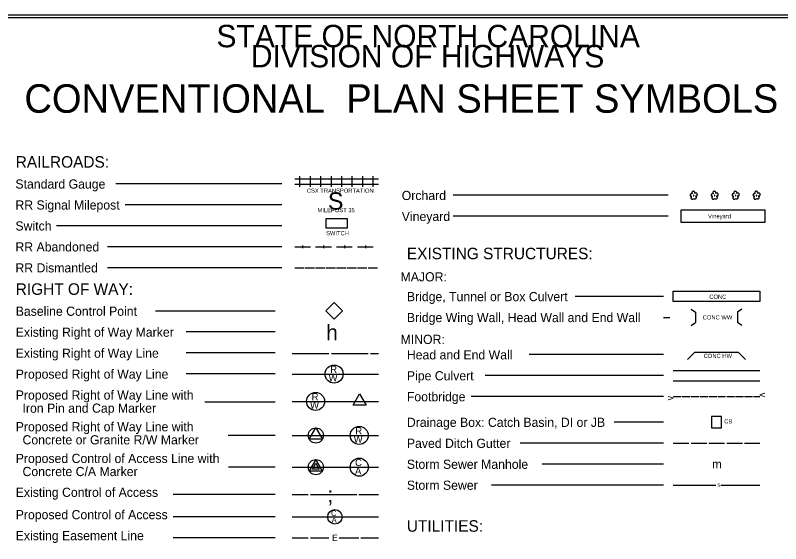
# Model space of a CAD drawing. Extents: x 1664524 to 1666208, y 587901 to 592296.
# Drawn here: x 1665085 to 1665816, y 589575 to 590079 of the extents above; entities that cross this region are included whole.
import ezdxf

# ---------------------------------------------------------------- set-up
doc = ezdxf.new("R2010")
doc.units = 0
for name, color, linetype in [('Default', 7, 'Continuous'), ('Prop Horizontal Alignment Tick Large', 7, 'Continuous'), ('Sheet Symbology CELL', 7, 'Continuous')]:
    doc.layers.add(name, color=color, linetype=linetype)

msp = doc.modelspace()

# ---------------------------------------------------------------- linework, layer by layer
at = {"layer": 'Default'}
msp.add_lwpolyline([(1665381.58, 589796.91), (1665389.4, 589804.73), (1665397.23, 589796.91), (1665389.4, 589789.08)], close=True, dxfattribs=at)
at = {"layer": 'Prop Horizontal Alignment Tick Large'}
msp.add_lwpolyline([(1664536.76, 589023.8), (1666203.26, 589023.8), (1666203.26, 590078.9), (1664536.76, 590078.9)], close=True, dxfattribs=at)
at = {"layer": 'Sheet Symbology CELL'}
for p, q in [((1665351.76, 589922.82), (1665361.76, 589922.82)), ((1665356.76, 589915.32), (1665356.76, 589925.32)), ((1665361.76, 589922.82), (1665371.76, 589922.82)), ((1665366.76, 589915.32), (1665366.76, 589925.32)), ((1665371.76, 589922.82), (1665381.76, 589922.82)), ((1665376.76, 589915.32), (1665376.76, 589925.32)), ((1665381.76, 589922.82), (1665391.76, 589922.82)), ((1665386.76, 589915.32), (1665386.76, 589925.32)), ((1665391.76, 589922.82), (1665401.76, 589922.82)), ((1665396.76, 589915.32), (1665396.76, 589925.32)), ((1665401.76, 589922.82), (1665411.76, 589922.82)), ((1665406.76, 589915.32), (1665406.76, 589925.32)), ((1665411.76, 589922.82), (1665421.76, 589922.82)), ((1665416.76, 589915.32), (1665416.76, 589925.32)), ((1665421.76, 589922.82), (1665431.76, 589922.82)), ((1665426.76, 589915.32), (1665426.76, 589925.32)), ((1665339.37, 589918.06), (1665180.95, 589918.06)), ((1665351.76, 589917.82), (1665361.76, 589917.82)), ((1665361.76, 589917.82), (1665371.76, 589917.82)), ((1665371.76, 589917.82), (1665381.76, 589917.82)), ((1665381.76, 589917.82), (1665391.76, 589917.82)), ((1665391.76, 589917.82), (1665401.76, 589917.82)), ((1665401.76, 589917.82), (1665411.76, 589917.82)), ((1665411.76, 589917.82), (1665421.76, 589917.82)), ((1665421.76, 589917.82), (1665431.76, 589917.82)), ((1665708.09, 589907.13), (1665503.15, 589907.13)), ((1665339.37, 589898.06), (1665189.82, 589898.06)), ((1665708.09, 589887.13), (1665503.15, 589887.13)), ((1665339.37, 589878.06), (1665124.45, 589878.06)), ((1665339.37, 589858.06), (1665173.2, 589858.06)), ((1665351.76, 589858.06), (1665366.76, 589858.06)), ((1665359.26, 589859.31), (1665359.26, 589856.81)), ((1665371.76, 589858.06), (1665386.76, 589858.06)), ((1665379.26, 589859.31), (1665379.26, 589856.81)), ((1665391.76, 589858.06), (1665406.76, 589858.06)), ((1665399.26, 589859.31), (1665399.26, 589856.81)), ((1665411.76, 589858.06), (1665426.76, 589858.06)), ((1665419.26, 589859.31), (1665419.26, 589856.81)), ((1665339.37, 589838.06), (1665173.2, 589838.06)), ((1665339.37, 589838.06), (1665173.2, 589838.06)), ((1665351.76, 589838.06), (1665360.76, 589838.06)), ((1665361.76, 589838.06), (1665370.76, 589838.06)), ((1665371.76, 589838.06), (1665380.76, 589838.06)), ((1665381.76, 589838.06), (1665390.76, 589838.06)), ((1665391.76, 589838.06), (1665400.76, 589838.06)), ((1665401.76, 589838.06), (1665410.76, 589838.06)), ((1665411.76, 589838.06), (1665420.76, 589838.06)), ((1665421.76, 589838.06), (1665430.76, 589838.06)), ((1665703.77, 589810.67), (1665619.35, 589810.67)), ((1665333.23, 589796.71), (1665219.02, 589796.71)), ((1665730.22, 589798.53), (1665734.32, 589795.67)), ((1665734.32, 589795.67), (1665734.32, 589785.67)), ((1665778.42, 589798.53), (1665774.32, 589795.67)), ((1665774.32, 589795.67), (1665774.32, 589785.67)), ((1665703.77, 589790.67), (1665709.76, 589790.67)), ((1665730.22, 589782.81), (1665734.32, 589785.67)), ((1665778.42, 589782.81), (1665774.32, 589785.67)), ((1665333.23, 589776.71), (1665248.29, 589776.71)), ((1665333.23, 589756.71), (1665248.29, 589756.71)), ((1665349.26, 589756.14), (1665384.26, 589756.14)), ((1665386.76, 589756.14), (1665421.76, 589756.14)), ((1665424.26, 589756.14), (1665431.76, 589756.14)), ((1665703.77, 589755.1), (1665575.47, 589755.1)), ((1665726.62, 589750.52), (1665733.7, 589757.6)), ((1665733.7, 589757.6), (1665774.95, 589757.6)), ((1665774.95, 589757.6), (1665782.02, 589750.52)), ((1665333.23, 589736.71), (1665248.29, 589736.71)), ((1665349.26, 589736.59), (1665431.76, 589736.59)), ((1665713.07, 589740.1), (1665795.57, 589740.1)), ((1665703.77, 589735.1), (1665533.59, 589735.1)), ((1665713.07, 589730.1), (1665795.57, 589730.1)), ((1665703.77, 589715.1), (1665520.3, 589715.1)), ((1665713.07, 589715.1), (1665720.57, 589715.1)), ((1665721.57, 589715.1), (1665729.07, 589715.1)), ((1665730.07, 589715.1), (1665737.57, 589715.1)), ((1665738.57, 589715.1), (1665746.07, 589715.1)), ((1665747.07, 589715.1), (1665754.57, 589715.1)), ((1665755.57, 589715.1), (1665763.07, 589715.1)), ((1665764.07, 589715.1), (1665771.57, 589715.1)), ((1665772.57, 589715.1), (1665780.07, 589715.1)), ((1665781.07, 589715.1), (1665788.57, 589715.1)), ((1665789.57, 589715.1), (1665795.57, 589715.1)), ((1665333.23, 589709.86), (1665266.12, 589709.86)), ((1665349.26, 589710.46), (1665431.76, 589710.46)), ((1665413.71, 589710.46), (1665413.71, 589710.46)), ((1665703.77, 589690.67), (1665656.57, 589690.67)), ((1665333.23, 589677.82), (1665288.24, 589677.82)), ((1665349.26, 589677.96), (1665431.76, 589677.96)), ((1665371.96, 589677.96), (1665371.96, 589677.96)), ((1665703.77, 589670.67), (1665566.82, 589670.67)), ((1665713.07, 589670.67), (1665728.07, 589670.67)), ((1665730.07, 589670.67), (1665745.07, 589670.67)), ((1665747.07, 589670.67), (1665762.07, 589670.67)), ((1665764.07, 589670.67), (1665779.07, 589670.67)), ((1665781.07, 589670.67), (1665795.57, 589670.67)), ((1665703.77, 589650.67), (1665588.1, 589650.67)), ((1665333.23, 589647.58), (1665288.61, 589647.58)), ((1665349.26, 589647.72), (1665431.76, 589647.72)), ((1665371.96, 589647.72), (1665371.96, 589647.72)), ((1665703.77, 589630.67), (1665539.57, 589630.67)), ((1665713.07, 589630.67), (1665753.6, 589630.67)), ((1665758.6, 589630.67), (1665795.57, 589630.67)), ((1665333.23, 589621.64), (1665235.68, 589621.64)), ((1665349.26, 589621.64), (1665364.72, 589621.64)), ((1665366.72, 589621.64), (1665411.13, 589621.64)), ((1665413.13, 589621.64), (1665431.76, 589621.64)), ((1665333.23, 589600.29), (1665235.68, 589600.29)), ((1665349.26, 589600.29), (1665431.76, 589600.29)), ((1665333.23, 589580.29), (1665235.68, 589580.29)), ((1665349.26, 589580.29), (1665364.77, 589580.29)), ((1665366.77, 589580.29), (1665384.27, 589580.29)), ((1665394.27, 589580.29), (1665413.02, 589580.29)), ((1665415.02, 589580.29), (1665431.76, 589580.29))]:
    msp.add_line(p, q, dxfattribs=at)
for points in [[(1666190.76, 590076.35), (1664690.76, 590076.35), (1664690.76, 589027.37), (1666190.76, 589027.37)], [(1665381.76, 589885.02), (1665401.76, 589885.02), (1665401.76, 589875.92), (1665381.76, 589875.92)], [(1665407.46, 589706.86), (1665413.71, 589717.66), (1665419.96, 589706.86)], [(1665749.51, 589685.36), (1665759.12, 589685.36), (1665759.12, 589695.99), (1665749.51, 589695.99)], [(1665365.71, 589674.36), (1665371.96, 589685.16), (1665378.21, 589674.36)], [(1665365.71, 589644.12), (1665378.21, 589644.12), (1665371.96, 589654.92)], [(1665368.69, 589645.83), (1665371.96, 589651.48), (1665375.23, 589645.83)]]:
    msp.add_lwpolyline(points, close=True, dxfattribs=at)
for points in [[(1665733.53, 589908.88), (1665733.68, 589909.18), (1665733.73, 589909.48), (1665733.68, 589909.78), (1665733.63, 589910.08), (1665733.48, 589910.33), (1665733.33, 589910.58), (1665733.08, 589910.78), (1665732.83, 589910.93), (1665732.48, 589911.03), (1665732.23, 589911.03), (1665731.93, 589910.98), (1665731.63, 589910.88), (1665731.38, 589910.73), (1665731.13, 589910.53), (1665730.98, 589910.23), (1665730.88, 589909.98), (1665730.83, 589909.68), (1665730.83, 589909.38), (1665730.88, 589909.08), (1665731.03, 589908.83), (1665731.23, 589908.53), (1665730.98, 589908.68), (1665730.68, 589908.73), (1665730.38, 589908.73), (1665730.13, 589908.63), (1665729.88, 589908.53), (1665729.63, 589908.33), (1665729.43, 589908.13), (1665729.28, 589907.88), (1665729.23, 589907.63), (1665729.18, 589907.28), (1665729.23, 589907.03), (1665729.33, 589906.78), (1665729.53, 589906.53), (1665729.68, 589906.33), (1665729.93, 589906.18), (1665730.23, 589906.03), (1665730.48, 589905.98), (1665730.78, 589905.98), (1665730.53, 589905.88), (1665730.28, 589905.68), (1665730.13, 589905.48), (1665730.03, 589905.18), (1665729.93, 589904.88), (1665729.93, 589904.63), (1665729.98, 589904.33), (1665730.13, 589904.08), (1665730.28, 589903.83), (1665730.48, 589903.63), (1665730.73, 589903.48), (1665730.98, 589903.38), (1665731.28, 589903.38), (1665731.58, 589903.38), (1665731.83, 589903.43), (1665732.08, 589903.63), (1665732.33, 589903.78), (1665732.58, 589904.23)], [(1665732.68, 589907.13), (1665732.53, 589907.13), (1665732.43, 589907.08), (1665732.33, 589907.03), (1665732.33, 589906.88), (1665732.33, 589906.78), (1665732.43, 589906.68), (1665732.58, 589906.68), (1665732.68, 589906.68), (1665732.78, 589906.78), (1665732.83, 589906.93), (1665732.78, 589907.03), (1665732.68, 589907.13)], [(1665732.58, 589904.23), (1665733.18, 589903.88), (1665733.48, 589903.78), (1665733.78, 589903.73), (1665734.08, 589903.78), (1665734.33, 589903.88), (1665734.58, 589904.03), (1665734.83, 589904.23), (1665734.98, 589904.48), (1665735.08, 589904.73), (1665735.18, 589905.03), (1665735.13, 589905.33), (1665735.08, 589905.63), (1665734.88, 589905.93), (1665734.73, 589906.13), (1665734.48, 589906.28), (1665734.18, 589906.43), (1665734.48, 589906.38), (1665734.83, 589906.38), (1665735.08, 589906.48), (1665735.38, 589906.63), (1665735.63, 589906.78), (1665735.83, 589907.03), (1665735.98, 589907.33), (1665736.03, 589907.63), (1665736.08, 589907.93), (1665736.03, 589908.23), (1665735.93, 589908.53), (1665735.73, 589908.78), (1665735.48, 589909.03), (1665735.23, 589909.18), (1665734.93, 589909.28), (1665734.63, 589909.33), (1665734.33, 589909.33), (1665734.03, 589909.23), (1665733.78, 589909.08), (1665733.53, 589908.88)], [(1665753.53, 589908.88), (1665753.68, 589909.18), (1665753.73, 589909.48), (1665753.68, 589909.78), (1665753.63, 589910.08), (1665753.48, 589910.33), (1665753.33, 589910.58), (1665753.08, 589910.78), (1665752.83, 589910.93), (1665752.48, 589911.03), (1665752.23, 589911.03), (1665751.93, 589910.98), (1665751.63, 589910.88), (1665751.38, 589910.73), (1665751.13, 589910.53), (1665750.98, 589910.23), (1665750.88, 589909.98), (1665750.83, 589909.68), (1665750.83, 589909.38), (1665750.88, 589909.08), (1665751.03, 589908.83), (1665751.23, 589908.53), (1665750.98, 589908.68), (1665750.68, 589908.73), (1665750.38, 589908.73), (1665750.13, 589908.63), (1665749.88, 589908.53), (1665749.63, 589908.33), (1665749.43, 589908.13), (1665749.28, 589907.88), (1665749.23, 589907.63), (1665749.18, 589907.28), (1665749.23, 589907.03), (1665749.33, 589906.78), (1665749.53, 589906.53), (1665749.68, 589906.33), (1665749.93, 589906.18), (1665750.23, 589906.03), (1665750.48, 589905.98), (1665750.78, 589905.98), (1665750.53, 589905.88), (1665750.28, 589905.68), (1665750.13, 589905.48), (1665750.03, 589905.18), (1665749.93, 589904.88), (1665749.93, 589904.63), (1665749.98, 589904.33), (1665750.13, 589904.08), (1665750.28, 589903.83), (1665750.48, 589903.63), (1665750.73, 589903.48), (1665750.98, 589903.38), (1665751.28, 589903.38), (1665751.58, 589903.38), (1665751.83, 589903.43), (1665752.08, 589903.63), (1665752.33, 589903.78), (1665752.58, 589904.23)], [(1665752.68, 589907.13), (1665752.53, 589907.13), (1665752.43, 589907.08), (1665752.33, 589907.03), (1665752.33, 589906.88), (1665752.33, 589906.78), (1665752.43, 589906.68), (1665752.58, 589906.68), (1665752.68, 589906.68), (1665752.78, 589906.78), (1665752.83, 589906.93), (1665752.78, 589907.03), (1665752.68, 589907.13)], [(1665752.58, 589904.23), (1665753.18, 589903.88), (1665753.48, 589903.78), (1665753.78, 589903.73), (1665754.08, 589903.78), (1665754.33, 589903.88), (1665754.58, 589904.03), (1665754.83, 589904.23), (1665754.98, 589904.48), (1665755.08, 589904.73), (1665755.18, 589905.03), (1665755.13, 589905.33), (1665755.08, 589905.63), (1665754.88, 589905.93), (1665754.73, 589906.13), (1665754.48, 589906.28), (1665754.18, 589906.43), (1665754.48, 589906.38), (1665754.83, 589906.38), (1665755.08, 589906.48), (1665755.38, 589906.63), (1665755.63, 589906.78), (1665755.83, 589907.03), (1665755.98, 589907.33), (1665756.03, 589907.63), (1665756.08, 589907.93), (1665756.03, 589908.23), (1665755.93, 589908.53), (1665755.73, 589908.78), (1665755.48, 589909.03), (1665755.23, 589909.18), (1665754.93, 589909.28), (1665754.63, 589909.33), (1665754.33, 589909.33), (1665754.03, 589909.23), (1665753.78, 589909.08), (1665753.53, 589908.88)], [(1665773.53, 589908.88), (1665773.68, 589909.18), (1665773.73, 589909.48), (1665773.68, 589909.78), (1665773.63, 589910.08), (1665773.48, 589910.33), (1665773.33, 589910.58), (1665773.08, 589910.78), (1665772.83, 589910.93), (1665772.48, 589911.03), (1665772.23, 589911.03), (1665771.93, 589910.98), (1665771.63, 589910.88), (1665771.38, 589910.73), (1665771.13, 589910.53), (1665770.98, 589910.23), (1665770.88, 589909.98), (1665770.83, 589909.68), (1665770.83, 589909.38), (1665770.88, 589909.08), (1665771.03, 589908.83), (1665771.23, 589908.53), (1665770.98, 589908.68), (1665770.68, 589908.73), (1665770.38, 589908.73), (1665770.13, 589908.63), (1665769.88, 589908.53), (1665769.63, 589908.33), (1665769.43, 589908.13), (1665769.28, 589907.88), (1665769.23, 589907.63), (1665769.18, 589907.28), (1665769.23, 589907.03), (1665769.33, 589906.78), (1665769.53, 589906.53), (1665769.68, 589906.33), (1665769.93, 589906.18), (1665770.23, 589906.03), (1665770.48, 589905.98), (1665770.78, 589905.98), (1665770.53, 589905.88), (1665770.28, 589905.68), (1665770.13, 589905.48), (1665770.03, 589905.18), (1665769.93, 589904.88), (1665769.93, 589904.63), (1665769.98, 589904.33), (1665770.13, 589904.08), (1665770.28, 589903.83), (1665770.48, 589903.63), (1665770.73, 589903.48), (1665770.98, 589903.38), (1665771.28, 589903.38), (1665771.58, 589903.38), (1665771.83, 589903.43), (1665772.08, 589903.63), (1665772.33, 589903.78), (1665772.58, 589904.23)], [(1665772.68, 589907.13), (1665772.53, 589907.13), (1665772.43, 589907.08), (1665772.33, 589907.03), (1665772.33, 589906.88), (1665772.33, 589906.78), (1665772.43, 589906.68), (1665772.58, 589906.68), (1665772.68, 589906.68), (1665772.78, 589906.78), (1665772.83, 589906.93), (1665772.78, 589907.03), (1665772.68, 589907.13)], [(1665772.58, 589904.23), (1665773.18, 589903.88), (1665773.48, 589903.78), (1665773.78, 589903.73), (1665774.08, 589903.78), (1665774.33, 589903.88), (1665774.58, 589904.03), (1665774.83, 589904.23), (1665774.98, 589904.48), (1665775.08, 589904.73), (1665775.18, 589905.03), (1665775.13, 589905.33), (1665775.08, 589905.63), (1665774.88, 589905.93), (1665774.73, 589906.13), (1665774.48, 589906.28), (1665774.18, 589906.43), (1665774.48, 589906.38), (1665774.83, 589906.38), (1665775.08, 589906.48), (1665775.38, 589906.63), (1665775.63, 589906.78), (1665775.83, 589907.03), (1665775.98, 589907.33), (1665776.03, 589907.63), (1665776.08, 589907.93), (1665776.03, 589908.23), (1665775.93, 589908.53), (1665775.73, 589908.78), (1665775.48, 589909.03), (1665775.23, 589909.18), (1665774.93, 589909.28), (1665774.63, 589909.33), (1665774.33, 589909.33), (1665774.03, 589909.23), (1665773.78, 589909.08), (1665773.53, 589908.88)], [(1665793.53, 589908.88), (1665793.68, 589909.18), (1665793.73, 589909.48), (1665793.68, 589909.78), (1665793.63, 589910.08), (1665793.48, 589910.33), (1665793.33, 589910.58), (1665793.08, 589910.78), (1665792.83, 589910.93), (1665792.48, 589911.03), (1665792.23, 589911.03), (1665791.93, 589910.98), (1665791.63, 589910.88), (1665791.38, 589910.73), (1665791.13, 589910.53), (1665790.98, 589910.23), (1665790.88, 589909.98), (1665790.83, 589909.68), (1665790.83, 589909.38), (1665790.88, 589909.08), (1665791.03, 589908.83), (1665791.23, 589908.53), (1665790.98, 589908.68), (1665790.68, 589908.73), (1665790.38, 589908.73), (1665790.13, 589908.63), (1665789.88, 589908.53), (1665789.63, 589908.33), (1665789.43, 589908.13), (1665789.28, 589907.88), (1665789.23, 589907.63), (1665789.18, 589907.28), (1665789.23, 589907.03), (1665789.33, 589906.78), (1665789.53, 589906.53), (1665789.68, 589906.33), (1665789.93, 589906.18), (1665790.23, 589906.03), (1665790.48, 589905.98), (1665790.78, 589905.98), (1665790.53, 589905.88), (1665790.28, 589905.68), (1665790.13, 589905.48), (1665790.03, 589905.18), (1665789.93, 589904.88), (1665789.93, 589904.63), (1665789.98, 589904.33), (1665790.13, 589904.08), (1665790.28, 589903.83), (1665790.48, 589903.63), (1665790.73, 589903.48), (1665790.98, 589903.38), (1665791.28, 589903.38), (1665791.58, 589903.38), (1665791.83, 589903.43), (1665792.08, 589903.63), (1665792.33, 589903.78), (1665792.58, 589904.23)], [(1665792.68, 589907.13), (1665792.53, 589907.13), (1665792.43, 589907.08), (1665792.33, 589907.03), (1665792.33, 589906.88), (1665792.33, 589906.78), (1665792.43, 589906.68), (1665792.58, 589906.68), (1665792.68, 589906.68), (1665792.78, 589906.78), (1665792.83, 589906.93), (1665792.78, 589907.03), (1665792.68, 589907.13)], [(1665792.58, 589904.23), (1665793.18, 589903.88), (1665793.48, 589903.78), (1665793.78, 589903.73), (1665794.08, 589903.78), (1665794.33, 589903.88), (1665794.58, 589904.03), (1665794.83, 589904.23), (1665794.98, 589904.48), (1665795.08, 589904.73), (1665795.18, 589905.03), (1665795.13, 589905.33), (1665795.08, 589905.63), (1665794.88, 589905.93), (1665794.73, 589906.13), (1665794.48, 589906.28), (1665794.18, 589906.43), (1665794.48, 589906.38), (1665794.83, 589906.38), (1665795.08, 589906.48), (1665795.38, 589906.63), (1665795.63, 589906.78), (1665795.83, 589907.03), (1665795.98, 589907.33), (1665796.03, 589907.63), (1665796.08, 589907.93), (1665796.03, 589908.23), (1665795.93, 589908.53), (1665795.73, 589908.78), (1665795.48, 589909.03), (1665795.23, 589909.18), (1665794.93, 589909.28), (1665794.63, 589909.33), (1665794.33, 589909.33), (1665794.03, 589909.23), (1665793.78, 589909.08), (1665793.53, 589908.88)], [(1665720.48, 589893.13), (1665800.48, 589893.13), (1665800.48, 589881.13), (1665720.48, 589881.13), (1665720.48, 589893.13)], [(1665713.07, 589815.67), (1665795.57, 589815.67), (1665795.57, 589805.67), (1665713.07, 589805.67), (1665713.07, 589815.67)]]:
    msp.add_lwpolyline(points, dxfattribs=at)
for centre, radius in [((1665389.38, 589736.59), 8.61), ((1665371.68, 589710.46), 8.61), ((1665371.96, 589677.96), 7.2), ((1665413.35, 589677.96), 8.61), ((1665413.35, 589647.72), 8.61), ((1665371.96, 589647.71), 7.2), ((1665390.13, 589600.29), 6.89)]:
    msp.add_circle(centre, radius, dxfattribs=at)

# ---------------------------------------------------------------- texts
for s, height, p in [('STATE OF NORTH CAROLINA', 21.419, (1665277.06, 590048.39)), ('DIVISION OF HIGHWAYS', 21.419, (1665309.91, 590029.22)), ('CONVENTIONAL  PLAN SHEET SYMBOLS', 27.2003, (1665093.75, 589985.9)), ('RAILROADS:', 11, (1665085.48, 589933.51)), ('Standard Gauge', 8.75, (1665085.2, 589913.54)), ('Orchard', 8.75, (1665453.93, 589902.61)), ('S', 16.5, (1665383.52, 589893.44)), ('RR Signal Milepost', 8.75, (1665085.2, 589893.54)), ('Vineyard', 8.75, (1665453.93, 589882.61)), ('Switch', 8.75, (1665085.2, 589873.54)), ('RR Abandoned', 8.75, (1665085.2, 589853.54)), ('EXISTING STRUCTURES:', 11, (1665458.81, 589846.12)), ('RR Dismantled', 8.75, (1665085.2, 589833.54)), ('MAJOR:', 8.75, (1665452.79, 589825)), ('RIGHT OF WAY:', 11, (1665085.48, 589812.16)), ('Bridge, Tunnel or Box Culvert', 8.75, (1665458.81, 589806.12)), ('CONC', 4, (1665747.51, 589808.31)), ('Baseline Control Point', 8.75, (1665085.48, 589792.16)), ('Bridge Wing Wall, Head Wall and End Wall', 8.75, (1665458.81, 589786.12)), ('Existing Right of Way Marker', 8.75, (1665085.48, 589772.16)), ('h', 15, (1665381.77, 589768.64)), ('MINOR:', 8.75, (1665452.79, 589765.3)), ('Existing Right of Way Line', 8.75, (1665085.48, 589752.16)), ('Head and End Wall', 8.75, (1665458.81, 589750.55)), ('R', 6.75, (1665385.67, 589737.6)), ('Proposed Right of Way Line', 8.75, (1665085.48, 589732.16)), ('W', 6.75, (1665384.13, 589729.65)), ('Pipe Culvert', 8.75, (1665458.81, 589730.56)), ('Proposed Right of Way Line with', 8.75, (1665085.48, 589712.16)), ('R', 6.75, (1665367.97, 589711.47)), ('Footbridge', 8.75, (1665458.82, 589710.56)), ('  Iron Pin and Cap Marker', 8.75, (1665085.48, 589699.66)), ('W', 6.75, (1665366.43, 589703.52)), ('Drainage Box: Catch Basin, DI or JB', 8.75, (1665458.82, 589686.13)), ('Proposed Right of Way Line with', 8.75, (1665085.48, 589681.94)), ('R', 6.75, (1665409.65, 589678.97)), ('  Concrete or Granite R/W Marker', 8.75, (1665085.48, 589669.44)), ('W', 6.75, (1665408.11, 589671.02)), ('Paved Ditch Gutter', 8.75, (1665458.82, 589666.12)), ('Proposed Control of Access Line with', 8.75, (1665085.48, 589651.69)), ('C', 6.75, (1665409.39, 589648.73)), ('Storm Sewer Manhole', 8.75, (1665458.82, 589646.12)), ('m', 8.25, (1665750.2, 589646.54)), ('  Concrete C/A Marker', 8.75, (1665085.48, 589639.19)), ('A', 6.75, (1665409.33, 589640.78)), ('Storm Sewer', 8.75, (1665458.82, 589626.12)), ('Existing Control of Access', 8.75, (1665085.48, 589619.37)), ('S', 3, (1665755.2, 589629.17)), (';', 15, (1665383.01, 589614.14)), ('Proposed Control of Access', 8.75, (1665085.48, 589598.02)), ('C', 5.4, (1665386.47, 589601.1)), ('A', 5.4, (1665387.01, 589594.61)), ('UTILITIES:', 11, (1665458.81, 589586.12)), ('Existing Easement Line', 8.75, (1665085.48, 589578.02)), ('E', 6, (1665387.47, 589577.29))]:
    msp.add_text(s, height=height, dxfattribs=at).set_placement(p)
for s, height, rotation, p in [('CSX TRANSPORTATION', 4, 360, (1665363.32, 589909.59)), ('MILEPOST 35', 4, 360, (1665373.51, 589891.01)), ('Vineyard', 4, 0.00002, (1665746.31, 589885.13)), ('SWITCH', 4, 360, (1665381.71, 589869.01)), ('CONC WW', 4, 0.00002, (1665741.2, 589788.67)), ('CONC HW', 4, 360, (1665742.12, 589751.94)), ('v', 6.6, 89.75915, (1665713.06, 589711.36)), ('v', 6.6, 270.24085, (1665795.56, 589718.84)), ('CB', 4, 360, (1665761.76, 589689.49))]:
    msp.add_text(s, height=height, rotation=rotation, dxfattribs=at).set_placement(p)

doc.saveas('drawing.dxf')
